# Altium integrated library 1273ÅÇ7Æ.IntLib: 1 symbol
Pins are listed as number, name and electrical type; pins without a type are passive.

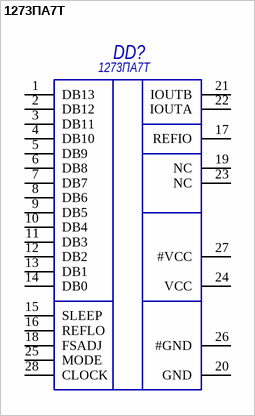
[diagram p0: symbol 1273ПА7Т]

## 1273ПА7Т
designator DD?
footprint 4119.28-1
pins: 1 DB13, 2 DB12, 3 DB11, 4 DB10, 5 DB9, 6 DB8, 7 DB7, 8 DB6, 9 DB5, 10 DB4, 11 DB3, 12 DB2, 13 DB1, 14 DB0, 15 SLEEP, 16 REFLO, 17 REFIO, 18 FSADJ, 19 NC, 20 GND, 21 IOUTB, 22 IOUTA, 23 NC, 24 VCC, 25 MODE, 26 #GND, 27 #VCC, 28 CLOCK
